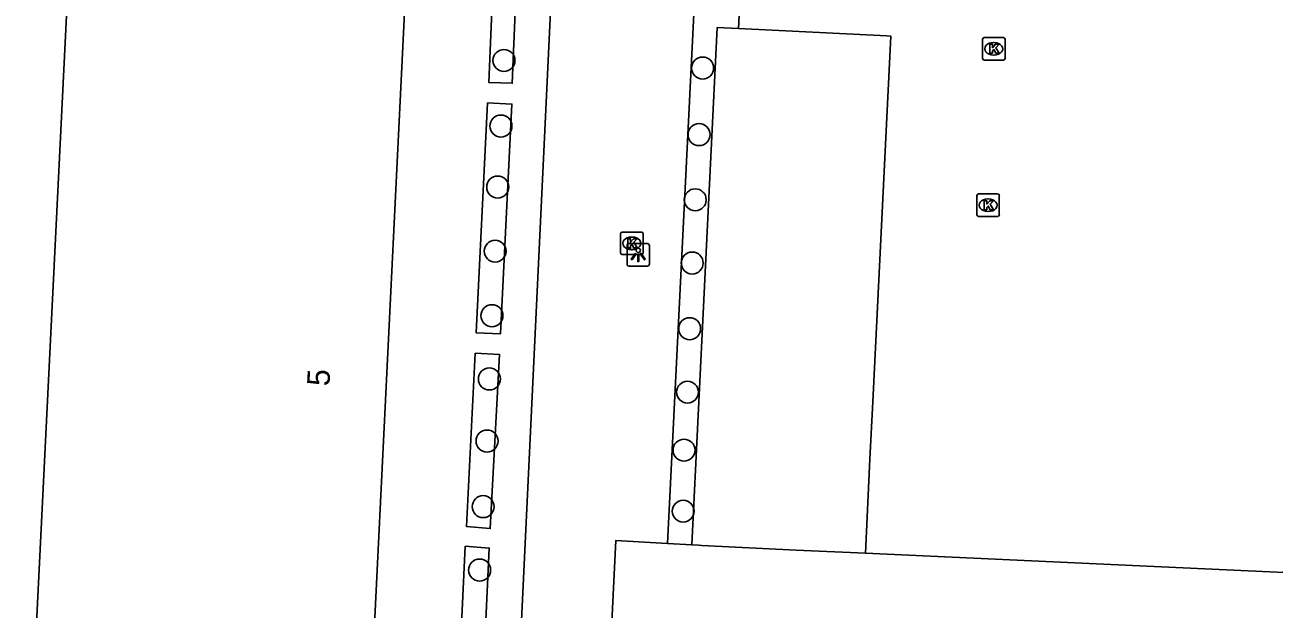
# Model space of a CAD drawing. Extents: x 161761 to 162722, y 384793 to 385405.
# Drawn here: x 162374.4 to 162429.9, y 385035.7 to 385061.7 of the extents above; entities that cross this region are included whole.
import ezdxf

# ---------------------------------------------------------------- set-up
doc = ezdxf.new("R2010")
doc.units = 0
for name, color, linetype in [('IMGEO_Boom', 7, 'Continuous'), ('IMGEO_Haag', 7, 'Continuous'), ('IMGEO_Kolk', 7, 'Continuous'), ('IMGEO_Lichtpunt', 7, 'Continuous'), ('IMGEO_Pand', 7, 'Continuous'), ('IMGEO_Pand_nummerreeks', 7, 'Continuous'), ('IMGEO_Voetpad_open', 7, 'Continuous')]:
    doc.layers.add(name, color=color, linetype=linetype)

msp = doc.modelspace()

# ---------------------------------------------------------------- linework, layer by layer
at = {"layer": 'IMGEO_Boom'}
for centre in [(162395.663, 385060.125), (162404.502, 385059.79), (162395.531, 385057.208), (162404.342, 385056.831), (162395.387, 385054.497), (162404.171, 385053.931), (162395.273, 385051.648), (162404.037, 385051.12), (162395.13, 385048.778), (162403.924, 385048.2), (162395.018, 385045.966), (162403.827, 385045.38), (162394.914, 385043.207), (162403.674, 385042.802), (162394.739, 385040.291), (162403.635, 385040.089), (162394.581, 385037.471)]:
    msp.add_circle(centre, 0.489, dxfattribs=at)
at = {"layer": 'IMGEO_Haag'}
msp.add_lwpolyline([(162405.414, 385063.918), (162406.21, 385063.87), (162406.102, 385061.54)], dxfattribs=at)
at = {"layer": 'IMGEO_Kolk'}
for p, q in [((162416.948, 385060.218), (162416.948, 385061.07)), ((162417.023, 385061.144), (162417.875, 385061.144)), ((162417.436, 385060.924), (162417.461, 385060.924)), ((162417.949, 385061.07), (162417.949, 385060.218)), ((162417.459, 385060.364), (162417.434, 385060.364)), ((162417.875, 385060.144), (162417.023, 385060.144)), ((162416.77, 385054.19), (162417.622, 385054.19)), ((162416.695, 385053.264), (162416.695, 385054.116)), ((162417.183, 385053.97), (162417.208, 385053.97)), ((162417.696, 385054.116), (162417.696, 385053.264)), ((162417.622, 385053.19), (162416.77, 385053.19)), ((162417.206, 385053.41), (162417.181, 385053.41)), ((162400.926, 385052.494), (162401.778, 385052.494)), ((162400.851, 385051.568), (162400.851, 385052.42)), ((162401.339, 385052.274), (162401.364, 385052.274)), ((162401.852, 385052.42), (162401.852, 385051.568)), ((162401.778, 385051.494), (162400.926, 385051.494)), ((162401.362, 385051.714), (162401.337, 385051.714))]:
    msp.add_line(p, q, dxfattribs=at)
for points in [[(162416.948, 385060.218), (162416.948, 385061.07)], [(162417.023, 385061.144), (162417.875, 385061.144)], [(162417.269, 385060.844), (162417.392, 385060.844), (162417.392, 385060.693), (162417.522, 385060.844), (162417.686, 385060.844), (162417.54, 385060.693), (162417.693, 385060.444), (162417.541, 385060.444), (162417.456, 385060.608), (162417.392, 385060.541), (162417.392, 385060.444), (162417.269, 385060.444), (162417.269, 385060.844)], [(162417.949, 385061.07), (162417.949, 385060.218)], [(162417.875, 385060.144), (162417.023, 385060.144)], [(162416.77, 385054.19), (162417.622, 385054.19)], [(162416.695, 385053.264), (162416.695, 385054.116)], [(162417.016, 385053.89), (162417.139, 385053.89), (162417.139, 385053.739), (162417.269, 385053.89), (162417.433, 385053.89), (162417.287, 385053.739), (162417.44, 385053.49), (162417.288, 385053.49), (162417.203, 385053.654), (162417.139, 385053.587), (162417.139, 385053.49), (162417.016, 385053.49), (162417.016, 385053.89)], [(162417.696, 385054.116), (162417.696, 385053.264)], [(162417.622, 385053.19), (162416.77, 385053.19)], [(162400.926, 385052.494), (162401.778, 385052.494)], [(162400.851, 385051.568), (162400.851, 385052.42)], [(162401.172, 385052.194), (162401.295, 385052.194), (162401.295, 385052.043), (162401.425, 385052.194), (162401.589, 385052.194), (162401.443, 385052.043), (162401.596, 385051.794), (162401.444, 385051.794), (162401.359, 385051.958), (162401.295, 385051.891), (162401.295, 385051.794), (162401.172, 385051.794), (162401.172, 385052.194)], [(162401.852, 385052.42), (162401.852, 385051.568)], [(162401.778, 385051.494), (162400.926, 385051.494)]]:
    msp.add_lwpolyline(points, dxfattribs=at)
for centre, start, end in [((162417.025, 385061.068), 91.552, 178.448), ((162417.025, 385061.068), 91.552, 178.448), ((162417.873, 385061.068), 1.552, 88.448), ((162417.873, 385061.068), 1.552, 88.448), ((162417.025, 385060.22), 181.552, 268.448), ((162417.025, 385060.22), 181.552, 268.448), ((162417.873, 385060.22), 271.552, 358.448), ((162417.873, 385060.22), 271.552, 358.448), ((162416.772, 385054.114), 91.552, 178.448), ((162416.772, 385054.114), 91.552, 178.448), ((162417.62, 385054.114), 1.552, 88.448), ((162417.62, 385054.114), 1.552, 88.448), ((162416.772, 385053.266), 181.552, 268.448), ((162416.772, 385053.266), 181.552, 268.448), ((162417.62, 385053.266), 271.552, 358.448), ((162417.62, 385053.266), 271.552, 358.448), ((162400.928, 385052.418), 91.552, 178.448), ((162400.928, 385052.418), 91.552, 178.448), ((162401.776, 385052.418), 1.552, 88.448), ((162401.776, 385052.418), 1.552, 88.448), ((162400.928, 385051.57), 181.552, 268.448), ((162400.928, 385051.57), 181.552, 268.448), ((162401.776, 385051.57), 271.552, 358.448), ((162401.776, 385051.57), 271.552, 358.448)]:
    msp.add_arc(centre, 0.0765, start, end, dxfattribs=at)
for centre, major_axis, ratio, start_param, end_param in [((162417.435, 385060.644), (-0.387, 0.002), 0.722429, 4.712389, 7.853982), ((162417.46, 385060.644), (-0.39, 0.002), 0.717154, 1.570796, 4.712389), ((162417.182, 385053.69), (-0.387, 0.002), 0.722429, 4.712389, 7.853982), ((162417.207, 385053.69), (-0.39, 0.002), 0.717154, 1.570796, 4.712389), ((162401.338, 385051.994), (-0.387, 0.002), 0.722429, 4.712389, 7.853982), ((162401.363, 385051.994), (-0.39, 0.002), 0.717154, 1.570796, 4.712389)]:
    msp.add_ellipse(centre, major_axis=major_axis, ratio=ratio, start_param=start_param, end_param=end_param, dxfattribs=at)
at = {"layer": 'IMGEO_Lichtpunt'}
for p, q in [((162402.041, 385051.984), (162401.233, 385051.984)), ((162402.041, 385051.984), (162401.233, 385051.984)), ((162401.139, 385051.889), (162401.139, 385051.082)), ((162401.139, 385051.889), (162401.139, 385051.082)), ((162402.135, 385051.082), (162402.135, 385051.889)), ((162402.135, 385051.082), (162402.135, 385051.889)), ((162401.233, 385050.988), (162402.041, 385050.988)), ((162401.233, 385050.988), (162402.041, 385050.988))]:
    msp.add_line(p, q, dxfattribs=at)
for points in [[(162401.513, 385051.553), (162401.552, 385051.525), (162401.364, 385051.263), (162401.326, 385051.29), (162401.513, 385051.553)], [(162401.615, 385051.505), (162401.662, 385051.505), (162401.662, 385051.183), (162401.615, 385051.183), (162401.615, 385051.505)], [(162401.725, 385051.525), (162401.763, 385051.552), (162401.95, 385051.29), (162401.911, 385051.262), (162401.725, 385051.525)]]:
    msp.add_lwpolyline(points, dxfattribs=at)
msp.add_circle((162401.638, 385051.687), 0.0994, dxfattribs=at)
for centre, start, end in [((162401.233, 385051.889), 90, 180), ((162401.233, 385051.889), 90, 180), ((162402.041, 385051.889), 0, 90), ((162402.041, 385051.889), 0, 90), ((162401.233, 385051.082), 180, 270), ((162401.233, 385051.082), 180, 270), ((162402.041, 385051.082), 270, 0), ((162402.041, 385051.082), 270, 360)]:
    msp.add_arc(centre, 0.0946, start, end, dxfattribs=at)
at = {"layer": 'IMGEO_Pand'}
for points in [[(162376.514, 385068.444), (162391.403, 385067.713), (162391.509, 385067.708), (162389.358, 385023.855), (162374.363, 385024.591), (162376.514, 385068.444)], [(162406.102, 385061.54), (162405.153, 385061.587), (162404.024, 385038.585)], [(162411.738, 385038.219), (162411.944, 385042.404), (162412.069, 385044.956), (162412.866, 385061.209), (162412.695, 385061.217), (162406.102, 385061.54)], [(162404.024, 385038.585), (162404.313, 385038.575), (162404.461, 385038.567), (162408.658, 385038.361), (162411.738, 385038.219)]]:
    msp.add_lwpolyline(points, dxfattribs=at)
at = {"layer": 'IMGEO_Voetpad_open'}
for points in [[(162395.555, 385016.551), (162399.452, 385098.409)], [(162395.326, 385067.279), (162396.368, 385067.236), (162396.033, 385059.11), (162394.991, 385059.153), (162395.326, 385067.279)], [(162402.942, 385038.647), (162404.199, 385063.991), (162405.414, 385063.918)], [(162394.94, 385058.24), (162396.02, 385058.186), (162395.509, 385047.97), (162394.429, 385048.024), (162394.94, 385058.24)], [(162394.385, 385047.109), (162395.464, 385047.056), (162395.052, 385039.311), (162394, 385039.407), (162394.385, 385047.109)], [(162408.86, 385034.446), (162400.443, 385034.857), (162400.64, 385038.778), (162402.942, 385038.647)], [(162404.024, 385038.585), (162402.942, 385038.647)], [(162393.94, 385038.526), (162395.011, 385038.448), (162394.137, 385019.5), (162393.057, 385019.542), (162393.94, 385038.526)], [(162411.738, 385038.219), (162436.14, 385037.094)]]:
    msp.add_lwpolyline(points, dxfattribs=at)

# ---------------------------------------------------------------- texts
at = {"layer": 'IMGEO_Pand_nummerreeks'}
msp.add_text('5', height=1, rotation=87.1919, dxfattribs=at).set_placement((162387.903, 385045.634))

doc.saveas('drawing.dxf')
